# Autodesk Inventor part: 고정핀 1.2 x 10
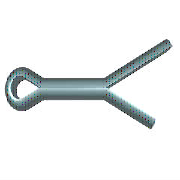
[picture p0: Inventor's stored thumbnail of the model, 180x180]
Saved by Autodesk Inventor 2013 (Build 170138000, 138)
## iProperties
IsCustomPart: 1
Created: 2012-02
Part Number: 고정핀 1.2 x 10
Material: 강철
Description: 분할 핀
Document SubType Name: Modeling
Standard: ISO 1234
Designer: test
Standard Revision: Second edition 1997-11-01
Standards Organization: ISO
Language: ko-KR
Size Designation: 1.2 x 10
Categories: <MemberInstance><Categories><Category DisplayName="조임쇠" InternalName="e4da775c-781d-43d5-af7c-5136215cf5a6" Mnemonic="FSTN"><Category DisplayName="핀" InternalNa
Density: 7.85 g/cm^3
Author: test
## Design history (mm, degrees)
sketch "스케치1"
  geometry: L1 (0, 0.5)-(5, 0.5); L2 (0, -0.5)-(5, -0.5); L3 (5, 0.5)-(10, 2.416); L4 (10, 2.416)-(10.167, 1.98); L5 (10.167, 1.98)-(5, 0); L6 (5, 0)-(12.667, -2.937); L7 (12.667, -2.937)-(12.5, -3.373); L8 (12.5, -3.373)-(5, -0.5); L9 (0, 0)-(-1.875, -0.484); L10 (0, 0)-(-1.875, 0.484); L11 (0, 0.5)-(0, -0.5); L12 (0, 0.5)-(-1.742, 0.966); L13 (0, -0.5)-(-1.742, -0.966); L14 (-3, 0)-(5, 0); L15 (5, 0.5)-(5, -0.5); A1 r 1 centre (-2, 0) between (-1.742, 0.966) and (-1.742, -0.966); A2 r 0.5 centre (-2, 0) between (-1.875, 0.484) and (-1.875, -0.484); 1 further point
  constraints: 30 end point, 5 point on circle, 4 parallel, 4 perpendicular, 4 point on line, 4 tangent, 2 centre point, 2 midpoint, 1 coincident, 1 horizontal
  dimensions: "d0" = 5 distance of L1.start L1.end (= MSIAB); "d1" = 10 horizontal distance of L1.start L3.end (= SNLG); "d2" = 159.037 deg angle of L1 L3; "d3" = 159.037 deg angle of L2 L8; "d4" = 2.5 horizontal distance of L3.end L7.end (= LGDIF); "d5" = 0.5 radius of A2 (= -0.5 x SNND1 + 0.5 x KBR); "d6" = 1 radius of A1 (= 0.5 x KBR); "d7" = 0.5 distance from line of L1 L9.start (= 0.5 x SNND1); "d8" = 0.5 distance between parallel lines of L2 L14 (= 0.5 x SNND1); "d9" = 2 distance from line of L11 A1.centre (= KOL - 0.5 x KBR)
extrude "본체" new body sketch "스케치1" stored distance "d10" = 1 (= SNND1); taper "d11" = 0 deg
workaxis "Work Axis1"
workplane "Work Plane1"
workplane "Work Plane3"
sketch "스케치5"
  geometry: L1 (12.5, -3.373)-(5, -0.5) reference; L2 (5, -0.5)-(0, -0.5) reference; L3 (0, -0.5)-(-1.742, -0.966) reference; L4 (-1.742, 0.966)-(0, 0.5) reference; L5 (0, 0.5)-(5, 0.5) reference; L6 (5, 0.5)-(10, 2.416) reference; L7 (10, 2.416)-(10.167, 1.98) reference; L8 (10.167, 1.98)-(5, 0) reference; L9 (5, 0)-(12.667, -2.937) reference; L10 (12.667, -2.937)-(12.5, -3.373) reference; L11 (0, 0)-(-1.875, 0.484) reference; L12 (-1.875, -0.484)-(0, 0) reference; A1 r 1 centre (-2, 0) between (-1.742, 0.966) and (-1.742, -0.966) reference; A2 r 0.5 centre (-2, 0) between (-1.875, 0.484) and (-1.875, -0.484) reference
  node "절단 모서리 투영1"
node "작업 평면3"
body "Solid1"
fillet "모깎기" dims "d12" = 0.35 (= 0.35 x SNND1)
other parameters: "SNND" = 1.2 [user parameter], "SNLG" = 10 [user parameter; used in 1 equation term], "SNND1" = 1 [user parameter; used in 5 equation terms], "KBR" = 2 [user parameter; used in 3 equation terms], "KOL" = 3 [user parameter; used in 1 equation term], "LGDIF" = 2.5 [user parameter; used in 1 equation term], "MSIAB" = 5 [user parameter; used in 1 equation term], "d15" = 0, "d16" = 0, "d17" = 0, "NNDMAX" = 5.5 [user parameter], "DSH" = 2.6 [user parameter], "NNDMIN" = 4.5 [user parameter], "d18" = -2.5
